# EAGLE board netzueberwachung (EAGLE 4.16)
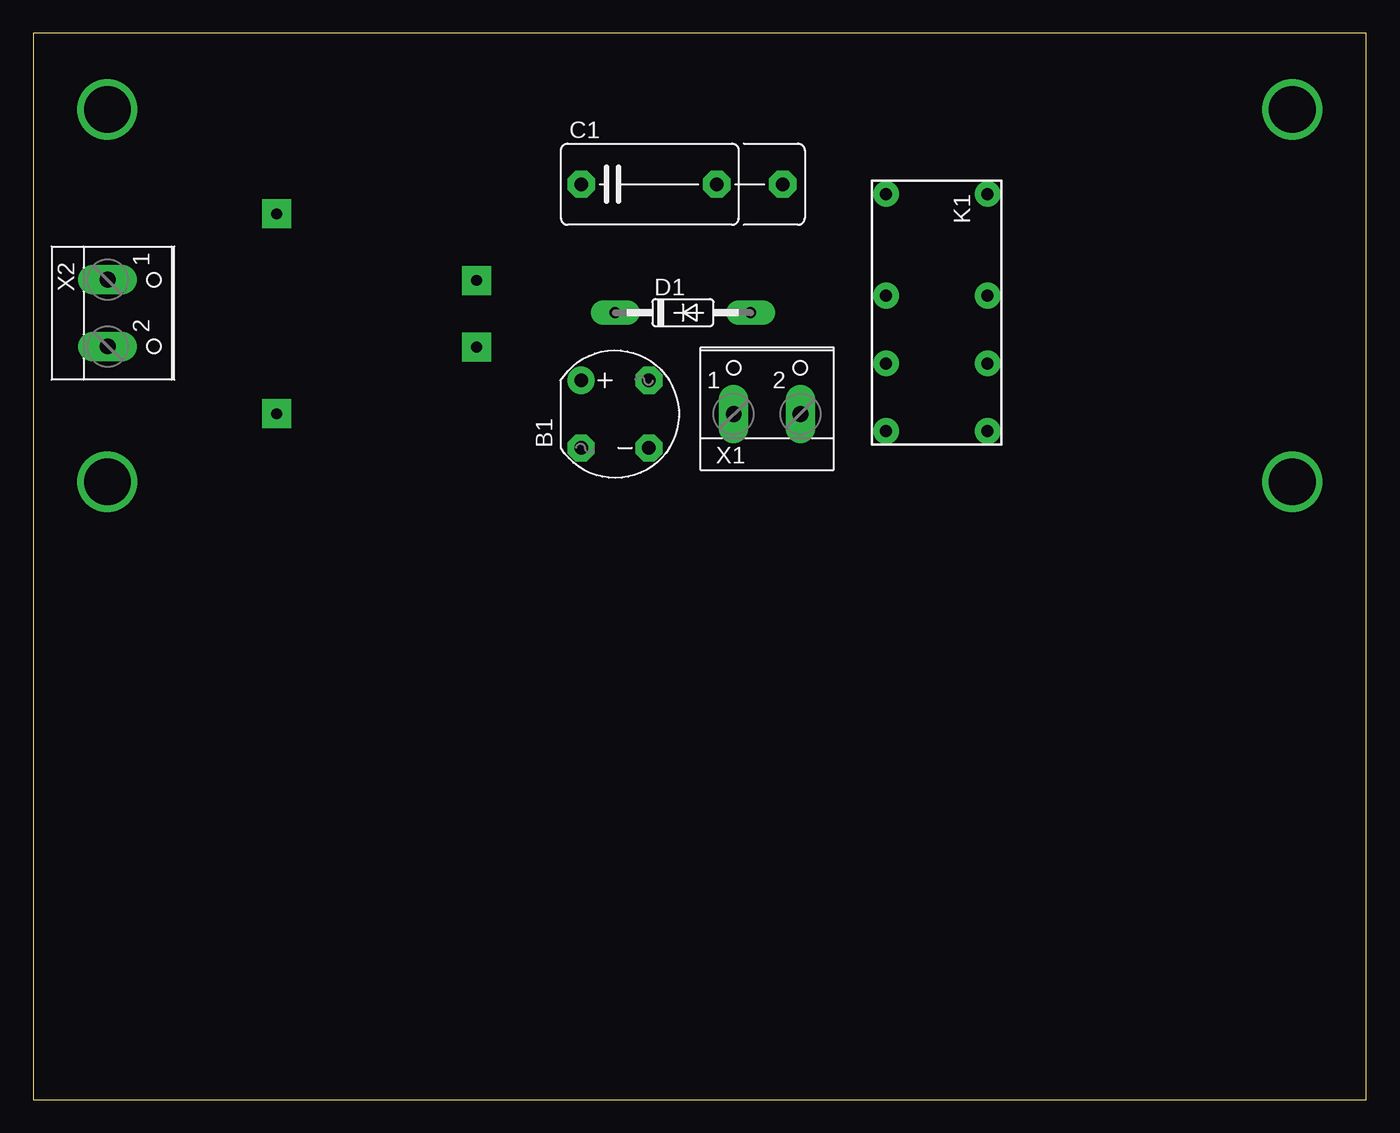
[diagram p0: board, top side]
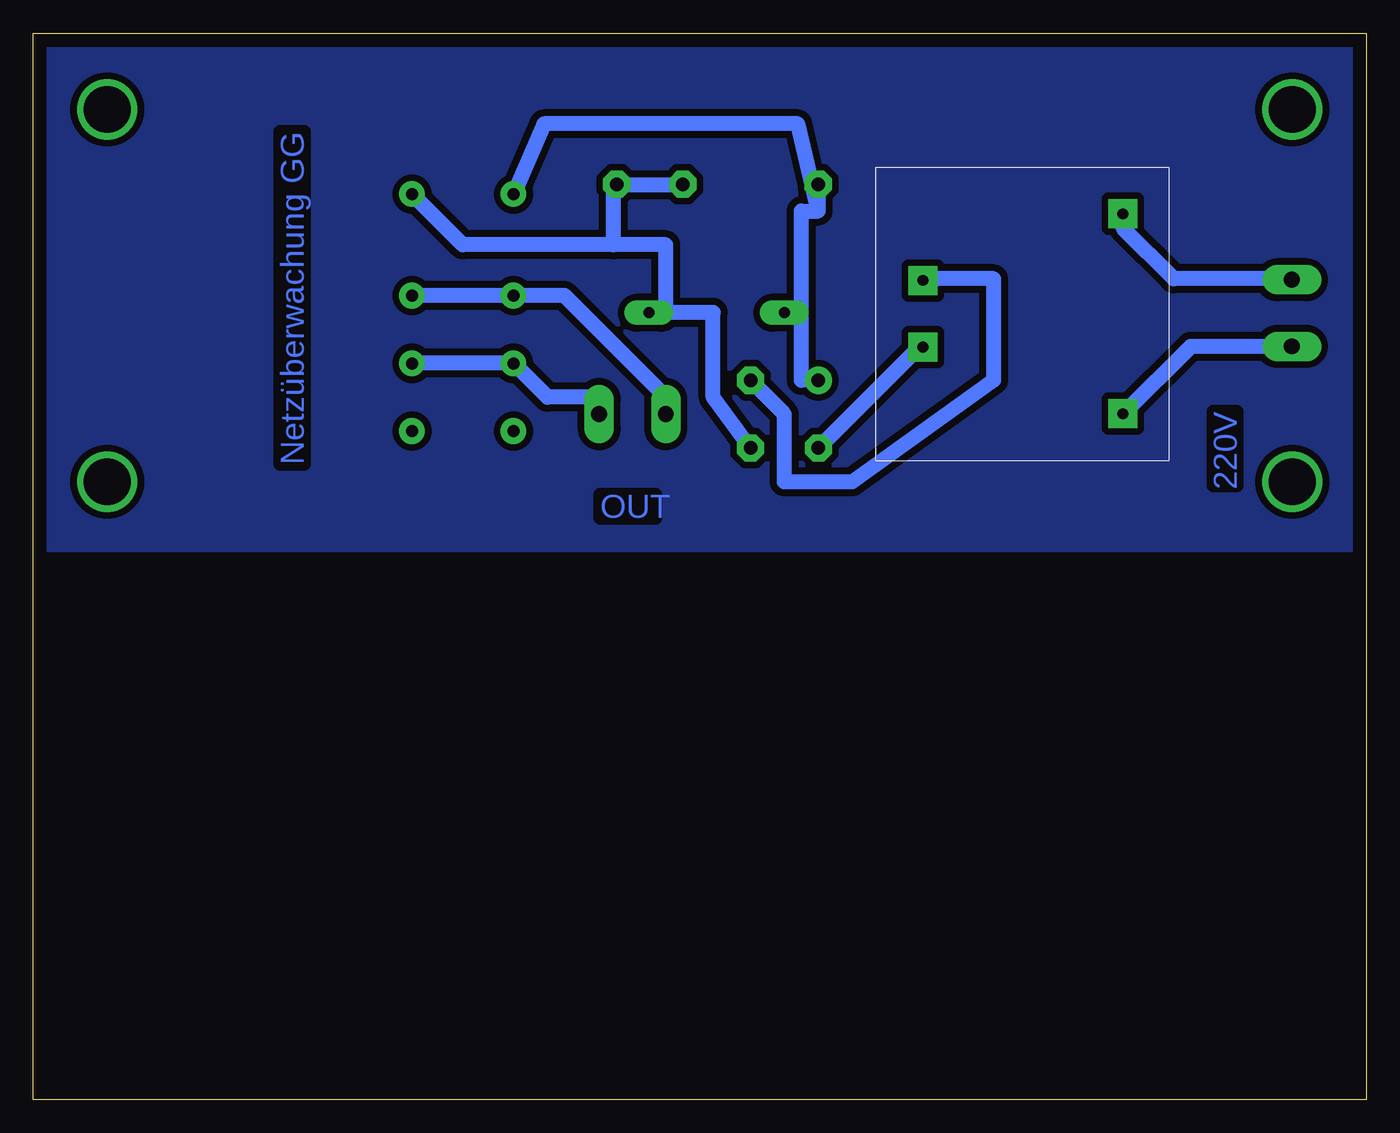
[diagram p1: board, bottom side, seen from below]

Size 100 x 80 mm. Coordinates in mm from the lower left corner, seen from the top.
Outline: 0,0 100,0 100,80 0,80 0,0
Copper layers (1*16): Top 0.035mm / dielectric 1.5mm / Bottom 0.035mm
Design rules "handyalarm0,0undmehr": minimum track width 45mil, minimum drill 24mil, track to track 20mil, track to pad 20mil, pad to pad 20mil, via to via 8mil, smd to smd 8mil, copper to edge 40mil, drill to drill 8mil, minimum pad ring 10mil, minimum via ring 8mil, stop-mask expansion 4mil, vias tented up to drill 0mil, thermal gap 10mil

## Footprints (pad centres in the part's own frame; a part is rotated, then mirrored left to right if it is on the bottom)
RB1A = drill 1.016 round: + -2.54,2.54 | drill 1.016 octagon: - 2.54,-2.54; AC1 2.54,2.54; AC2 -2.54,-2.54
C102_152-062X184 = drill 1.016 octagon: 1 -5.08,0; 2 5.08,0; 3 10.033,0
DO35-10 = drill 0.813 long: A 5.08,0; C -5.08,0
DS2Y = drill 0.9 round: 1 -8.89,-3.81; 4 -1.27,-3.81; 6 3.81,-3.81; 8 8.89,-3.81; 9 8.89,3.81; 11 3.81,3.81; 13 -1.27,3.81; 16 -8.89,3.81
TRAFO_GERTH_150-12-1 = drill 0.8 pad 2.184 square: 1 -7.495,-6.543; 4 7.505,-6.543; 6 2.505,8.457; 7 -2.495,8.457
W237-102 = drill 1.194 long: 1 -2.5,-1.27; 2 2.5,-1.27

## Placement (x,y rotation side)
B1  [RB1A]  43.64,51.42 0 top
C1  [C102_152-062X184]  46.19,68.68 0 top
D1  1N4148  [DO35-10]  48.73,59.04 0 top
K1  DS2Y-S-DC12V  [DS2Y]  67.78,59.05 270 top
U$1  TRAFO_GERTH_150-12-1  [TRAFO_GERTH_150-12-1]  24.8,58.95 90 bottom
X1  [W237-102]  55.05,52.7 0 top
X2  [W237-102]  6.84,59.01 270 top

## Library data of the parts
B1 = rectifier
C1 = rcl
D1 = diode
K1 = relay
U$1 = mylib-gg
X1 X2 = con-wago-500

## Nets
GND: B1.- C1.2 D1.A K1.16
N$1: U$1.4 X2.1
N$2: U$1.1 X2.2
N$3: B1.AC1 U$1.6
N$4: B1.AC2 U$1.7
N$5: K1.6 K1.11 X1.2
N$6: K1.4 K1.13 X1.1
VCC: B1.+ C1.1 D1.C K1.1

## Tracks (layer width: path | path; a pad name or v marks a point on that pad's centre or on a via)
GND
  Bottom 0.406: 52.54,64.13 56.47,64.13 | 51.47,68.63 51.47,68.67 C1.2
  Bottom 1.143: 52.54,59.05 52.54,64.13 67.78,64.13 K1.16 | 52.54,59.05 49,59.05 49,52.7 B1.- | 52.54,59.05 D1.A | 56.47,64.13 56.47,68.63 51.47,68.63
N$1
  Bottom 1.143: U$1.4 18.25,65.4 14.44,61.59 6.82,61.59 X2.1
N$2
  Bottom 1.143: U$1.1 18.25,51.43 13.17,56.51 6.82,56.51 X2.2
N$3
  Bottom 1.143: B1.AC1 43.65,51.43 43.65,46.35 38.57,46.35 27.95,53.97 27.95,61.59 32.22,61.59 U$1.6
N$4
  Bottom 1.143: B1.AC2 33.49,56.51 U$1.7
N$5
  Bottom 1.143: K1.6 61.43,52.7 57.62,52.7 X1.2 | K1.6 K1.11 | K1.6
N$6
  Bottom 1.143: K1.4 K1.13 | K1.4 60.16,60.32 52.54,52.7 X1.1 | K1.4
N$7  (via drill 3.5)
  other vias: 5.55,74.29
N$8  (via drill 3.5)
  other vias: 94.45,74.29
N$9  (via drill 3.5)
  other vias: 5.55,46.35
N$10  (via drill 3.5)
  other vias: 94.45,46.35
N$11
  pour Bottom: 0.47,79.37 99.53,79.37 99.53,41.27 0.47,41.27
VCC
  Bottom 1.143: 42.38,59.05 42.38,53.97 B1.+ | 41.11,66.67 42.65,73.21 61.7,73.21 K1.1 | 42.38,59.05 42.38,66.67 41.11,66.67 | 42.38,59.05 D1.C | 41.11,66.67 C1.1

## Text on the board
Bottom: Netzüberwachung GG | 220V | OUT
